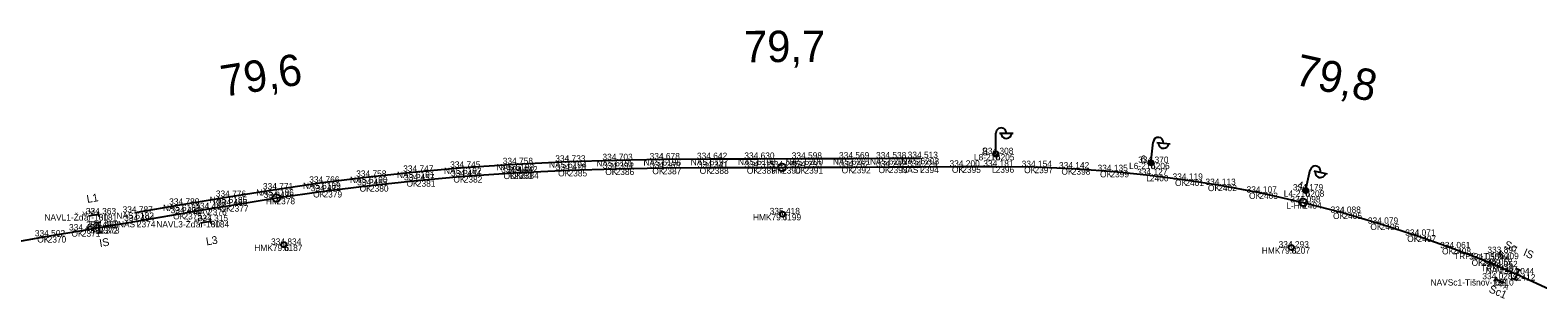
# Model space of a CAD drawing. Extents: x -621782 to -610392, y -1141853 to -1122321.
# Drawn here: x -614776.2 to -614487.1, y -1129952.4 to -1129901 of the extents above; entities that cross this region are included whole.
import ezdxf

# ---------------------------------------------------------------- set-up
doc = ezdxf.new("R2010")
doc.units = 0
for name, color, linetype in [('Vrstva 1', 7, 'Continuous'), ('Vrstva 14', 7, 'Continuous'), ('Vrstva 25', 7, 'Continuous'), ('Vrstva 3', 7, 'Continuous'), ('Vrstva 6', 7, 'Continuous'), ('Vrstva 60', 7, 'Continuous'), ('Vrstva 61', 7, 'Continuous'), ('Vrstva 62', 7, 'Continuous'), ('Vrstva 7', 7, 'Continuous')]:
    doc.layers.add(name, color=color, linetype=linetype)

msp = doc.modelspace()

# ---------------------------------------------------------------- linework, layer by layer
at = {"layer": 'Vrstva 1'}
msp.add_lwpolyline([(-614780.67, -1129941.78), (-614772.86, -1129940.43), (-614766.31, -1129939.31), (-614763.01, -1129938.75), (-614762.64, -1129938.69), (-614755.75, -1129937.51), (-614746.82, -1129936), (-614742.1, -1129935.2), (-614737.91, -1129934.51), (-614728.99, -1129933.09), (-614719.97, -1129931.79), (-614711.06, -1129930.68), (-614702.07, -1129929.73), (-614693.08, -1129928.94), (-614683.45, -1129928.28), (-614682.27, -1129928.21), (-614672.99, -1129927.77), (-614663.96, -1129927.5), (-614654.93, -1129927.35), (-614645.85, -1129927.29), (-614636.81, -1129927.26), (-614632.05, -1129927.24), (-614627.75, -1129927.22), (-614618.62, -1129927.18), (-614611.56, -1129927.14), (-614605.56, -1129927.12), (-614597.49, -1129927.09), (-614591.1, -1129927.08), (-614583.65, -1129927.15), (-614576.5, -1129927.44), (-614569.09, -1129927.95), (-614561.51, -1129928.71), (-614554.72, -1129929.6), (-614548.41, -1129930.59), (-614540.53, -1129932.07), (-614532.14, -1129933.94), (-614524.42, -1129935.93), (-614517.27, -1129938.02), (-614510.19, -1129940.31), (-614503.51, -1129942.7), (-614497.84, -1129944.89), (-614495.32, -1129945.92), (-614494.35, -1129946.33), (-614491.18, -1129947.69), (-614484.18, -1129950.86)], dxfattribs=at)
at = {"layer": 'Vrstva 14'}
msp.add_lwpolyline([(-614756.04, -1129935.88), (-614747.11, -1129934.37), (-614738.16, -1129932.87), (-614729.23, -1129931.45), (-614720.24, -1129930.16), (-614711.25, -1129929.03), (-614702.24, -1129928.07), (-614693.22, -1129927.29), (-614683.15, -1129926.61), (-614673.08, -1129926.12), (-614664.03, -1129925.84), (-614654.98, -1129925.69), (-614645.91, -1129925.63), (-614636.83, -1129925.59), (-614627.74, -1129925.56), (-614618.67, -1129925.52), (-614611.57, -1129925.49), (-614605.5, -1129925.45)], dxfattribs=at)
at = {"layer": 'Vrstva 25'}
for p, q in [((-614591.04, -1129924.19), (-614591.05, -1129920.69)), ((-614590.35, -1129920.69), (-614587.75, -1129920.68)), ((-614561.25, -1129925.88), (-614560.9, -1129922.39)), ((-614560.21, -1129922.46), (-614557.62, -1129922.72)), ((-614591.52, -1129924.84), (-614590.9, -1129924.21)), ((-614591.28, -1129925.13), (-614590.6, -1129924.45)), ((-614561.79, -1129926.47), (-614561.11, -1129925.91)), ((-614561.58, -1129926.78), (-614560.84, -1129926.18)), ((-614531.54, -1129931.16), (-614530.78, -1129927.74)), ((-614530.09, -1129927.89), (-614527.55, -1129928.46)), ((-614532.14, -1129931.69), (-614531.4, -1129931.21)), ((-614531.97, -1129932.02), (-614531.17, -1129931.51))]:
    msp.add_line(p, q, dxfattribs=at)
for centre in [(-614591.04, -1129924.69), (-614561.3, -1129926.37), (-614531.65, -1129931.65)]:
    msp.add_circle(centre, 0.5, dxfattribs=at)
for centre, start, end in [((-614590.05, -1129920.69), 0.0807, 180.0807), ((-614589.05, -1129920.7), 179.3782, 0.7833), ((-614559.91, -1129922.49), 354.2782, 174.2782), ((-614558.91, -1129922.6), 173.5756, 354.9808), ((-614529.8, -1129927.96), 347.4437, 167.4437), ((-614528.83, -1129928.19), 166.7411, 348.1463)]:
    msp.add_arc(centre, 1, start, end, dxfattribs=at)
at = {"layer": 'Vrstva 3'}
for p, q in [((-614763.67, -1129937.85), (-614762.68, -1129937.68)), ((-614763.17, -1129937.76), (-614762.84, -1129939.73)), ((-614763.33, -1129939.82), (-614762.34, -1129939.65)), ((-614490.79, -1129946.77), (-614491.57, -1129948.61)), ((-614491.24, -1129946.57), (-614490.33, -1129946.96)), ((-614492.03, -1129948.41), (-614491.11, -1129948.8))]:
    msp.add_line(p, q, dxfattribs=at)
at = {"layer": 'Vrstva 6'}
for p, q in [((-614765.03, -1129936.54), (-614763.08, -1129936.21)), ((-614763, -1129936.7), (-614763.16, -1129935.72)), ((-614743.57, -1129937.86), (-614741.62, -1129937.53)), ((-614741.53, -1129938.02), (-614741.7, -1129937.03)), ((-614494.55, -1129944.06), (-614494.17, -1129943.14)), ((-614495.13, -1129948.19), (-614495.52, -1129949.11)), ((-614493.51, -1129949.43), (-614495.33, -1129948.65))]:
    msp.add_line(p, q, dxfattribs=at)
at = {"layer": 'Vrstva 60'}
for p, q in [((-614683.15, -1129926.61), (-614683.15, -1129926.61)), ((-614673.08, -1129926.12), (-614673.08, -1129926.12)), ((-614664.03, -1129925.84), (-614664.03, -1129925.84)), ((-614654.98, -1129925.69), (-614654.98, -1129925.69)), ((-614645.91, -1129925.63), (-614645.91, -1129925.63)), ((-614636.83, -1129925.59), (-614636.83, -1129925.59)), ((-614627.74, -1129925.56), (-614627.74, -1129925.56)), ((-614618.67, -1129925.52), (-614618.67, -1129925.52)), ((-614611.57, -1129925.49), (-614611.57, -1129925.49)), ((-614605.5, -1129925.45), (-614605.5, -1129925.45)), ((-614591.04, -1129924.69), (-614591.04, -1129924.69)), ((-614561.3, -1129926.37), (-614561.3, -1129926.37)), ((-614711.25, -1129929.03), (-614711.25, -1129929.03)), ((-614702.24, -1129928.07), (-614702.24, -1129928.07)), ((-614693.22, -1129927.29), (-614693.22, -1129927.29)), ((-614693.08, -1129928.94), (-614693.08, -1129928.94)), ((-614683.45, -1129928.28), (-614683.45, -1129928.28)), ((-614682.27, -1129928.21), (-614682.27, -1129928.21)), ((-614672.99, -1129927.77), (-614672.99, -1129927.77)), ((-614663.96, -1129927.5), (-614663.96, -1129927.5)), ((-614654.93, -1129927.35), (-614654.93, -1129927.35)), ((-614645.85, -1129927.29), (-614645.85, -1129927.29)), ((-614636.81, -1129927.26), (-614636.81, -1129927.26)), ((-614632.05, -1129927.24), (-614632.05, -1129927.24)), ((-614627.75, -1129927.22), (-614627.75, -1129927.22)), ((-614618.62, -1129927.18), (-614618.62, -1129927.18)), ((-614611.56, -1129927.14), (-614611.56, -1129927.14)), ((-614605.56, -1129927.12), (-614605.56, -1129927.12)), ((-614597.49, -1129927.09), (-614597.49, -1129927.09)), ((-614591.1, -1129927.08), (-614591.1, -1129927.08)), ((-614583.65, -1129927.15), (-614583.65, -1129927.15)), ((-614576.5, -1129927.44), (-614576.5, -1129927.44)), ((-614569.09, -1129927.95), (-614569.09, -1129927.95)), ((-614561.51, -1129928.71), (-614561.51, -1129928.71)), ((-614554.72, -1129929.6), (-614554.72, -1129929.6)), ((-614729.23, -1129931.45), (-614729.23, -1129931.45)), ((-614720.24, -1129930.16), (-614720.24, -1129930.16)), ((-614719.97, -1129931.79), (-614719.97, -1129931.79)), ((-614711.06, -1129930.68), (-614711.06, -1129930.68)), ((-614702.07, -1129929.73), (-614702.07, -1129929.73)), ((-614548.41, -1129930.59), (-614548.41, -1129930.59)), ((-614540.53, -1129932.07), (-614540.53, -1129932.07)), ((-614531.65, -1129931.65), (-614531.65, -1129931.65)), ((-614747.11, -1129934.37), (-614747.11, -1129934.37)), ((-614742.1, -1129935.2), (-614742.1, -1129935.2)), ((-614738.16, -1129932.87), (-614738.16, -1129932.87)), ((-614737.91, -1129934.51), (-614737.91, -1129934.51)), ((-614728.99, -1129933.09), (-614728.99, -1129933.09)), ((-614532.14, -1129933.94), (-614532.14, -1129933.94)), ((-614763.08, -1129936.21), (-614763.08, -1129936.21)), ((-614756.04, -1129935.88), (-614756.04, -1129935.88)), ((-614755.75, -1129937.51), (-614755.75, -1129937.51)), ((-614746.82, -1129936), (-614746.82, -1129936)), ((-614741.62, -1129937.53), (-614741.62, -1129937.53)), ((-614631.96, -1129936.19), (-614631.96, -1129936.19)), ((-614524.42, -1129935.93), (-614524.42, -1129935.93)), ((-614517.27, -1129938.02), (-614517.27, -1129938.02)), ((-614772.86, -1129940.43), (-614772.86, -1129940.43)), ((-614766.31, -1129939.31), (-614766.31, -1129939.31)), ((-614763.01, -1129938.75), (-614763.01, -1129938.75)), ((-614762.64, -1129938.69), (-614762.64, -1129938.69)), ((-614510.19, -1129940.31), (-614510.19, -1129940.31)), ((-614727.57, -1129942.04), (-614727.57, -1129942.04)), ((-614534.39, -1129942.56), (-614534.39, -1129942.56)), ((-614503.51, -1129942.7), (-614503.51, -1129942.7)), ((-614494.36, -1129943.6), (-614494.36, -1129943.6)), ((-614497.84, -1129944.89), (-614497.84, -1129944.89)), ((-614495.32, -1129945.92), (-614495.32, -1129945.92)), ((-614494.35, -1129946.33), (-614494.35, -1129946.33)), ((-614495.33, -1129948.65), (-614495.33, -1129948.65)), ((-614491.18, -1129947.69), (-614491.18, -1129947.69))]:
    msp.add_line(p, q, dxfattribs=at)
at = {"layer": 'Vrstva 7'}
for p, q in [((-614632.01, -1129936.19), (-614631.91, -1129936.19)), ((-614727.61, -1129942.05), (-614727.52, -1129942.04)), ((-614534.44, -1129942.55), (-614534.34, -1129942.57))]:
    msp.add_line(p, q, dxfattribs=at)
for centre, radius in [((-614632.05, -1129927.24), 0.75), ((-614728.99, -1129933.09), 0.75), ((-614532.14, -1129933.94), 0.75), ((-614631.96, -1129936.19), 0.5), ((-614727.57, -1129942.04), 0.5), ((-614534.39, -1129942.56), 0.5)]:
    msp.add_circle(centre, radius, dxfattribs=at)

# ---------------------------------------------------------------- texts
at = {"layer": 'Vrstva 25'}
for s, rotation, p in [('8', 0.0807, (-614593.71, -1129924.95)), ('6', 354.2782, (-614563.4, -1129926.4)), ('4', 347.4437, (-614533.39, -1129931.29))]:
    msp.add_text(s, height=1.5, rotation=rotation, dxfattribs=at).set_placement(p)
at = {"layer": 'Vrstva 3'}
for rotation, p in [(9.6646, (-614762.81, -1129942.5)), (336.8123, (-614490.06, -1129944.08))]:
    msp.add_text('IS', height=1.5, rotation=rotation, dxfattribs=at).set_placement(p)
at = {"layer": 'Vrstva 6'}
for s, height, rotation, p in [('L1', 1.5, 9.7118, (-614765.24, -1129934.06)), ('  A A ', 1, 189.7118, (-614763.25, -1129935.22)), ('  A A ', 1, 189.6079, (-614741.78, -1129936.54)), ('L3', 1.5, 9.6079, (-614742.37, -1129942.18)), ('A A ', 1, 337.7412, (-614494.74, -1129944.53)), ('Sc', 1.5, 337.7412, (-614493.7, -1129942.58)), ('Sc1', 1.5, 336.8123, (-614496.65, -1129951.07)), ('  A A ', 1, 336.8123, (-614495.72, -1129949.57))]:
    msp.add_text(s, height=height, rotation=rotation, dxfattribs=at).set_placement(p)
at = {"layer": 'Vrstva 60'}
for s, p in [('6193', (-614683.15, -1129927.81)), ('6194', (-614673.08, -1129927.32)), ('6195', (-614664.03, -1129927.04)), ('6196', (-614654.98, -1129926.89)), ('6197', (-614645.91, -1129926.83)), ('6198', (-614636.83, -1129926.79)), ('6200', (-614627.74, -1129926.76)), ('6201', (-614618.67, -1129926.72)), ('6202', (-614611.57, -1129926.69)), ('6203', (-614605.5, -1129926.65)), ('6205', (-614591.04, -1129925.89)), ('6206', (-614561.3, -1129927.57)), ('6190', (-614711.25, -1129930.23)), ('6191', (-614702.24, -1129929.27)), ('6192', (-614693.22, -1129928.49)), ('2382', (-614693.08, -1129930.14)), ('2383', (-614683.45, -1129929.48)), ('2384', (-614682.27, -1129929.41)), ('2385', (-614672.99, -1129928.97)), ('2386', (-614663.96, -1129928.7)), ('2387', (-614654.93, -1129928.55)), ('2388', (-614645.85, -1129928.49)), ('2389', (-614636.81, -1129928.46)), ('2390', (-614632.05, -1129928.44)), ('2391', (-614627.75, -1129928.42)), ('2392', (-614618.62, -1129928.38)), ('2393', (-614611.56, -1129928.34)), ('2394', (-614605.56, -1129928.32)), ('2395', (-614597.49, -1129928.29)), ('2396', (-614591.1, -1129928.28)), ('2397', (-614583.65, -1129928.35)), ('2398', (-614576.5, -1129928.64)), ('2399', (-614569.09, -1129929.15)), ('2400', (-614561.51, -1129929.91)), ('2401', (-614554.72, -1129930.8)), ('6186', (-614729.23, -1129932.65)), ('6189', (-614720.24, -1129931.36)), ('2379', (-614719.97, -1129933)), ('2380', (-614711.06, -1129931.88)), ('2381', (-614702.07, -1129930.93)), ('2402', (-614548.41, -1129931.79)), ('2403', (-614540.53, -1129933.27)), ('6208', (-614531.65, -1129932.85)), ('6183', (-614747.11, -1129935.57)), ('2376', (-614742.1, -1129936.4)), ('6185', (-614738.16, -1129934.07)), ('2377', (-614737.91, -1129935.71)), ('2378', (-614728.99, -1129934.29)), ('2404', (-614532.14, -1129935.14)), ('6181', (-614763.08, -1129937.41)), ('6182', (-614756.04, -1129937.08)), ('2374', (-614755.75, -1129938.71)), ('2375', (-614746.82, -1129937.2)), ('6184', (-614741.62, -1129938.73)), ('6199', (-614631.96, -1129937.39)), ('2405', (-614524.42, -1129937.13)), ('2406', (-614517.27, -1129939.22)), ('2370', (-614772.86, -1129941.63)), ('2371', (-614766.31, -1129940.51)), ('2372', (-614763.01, -1129939.95)), ('2373', (-614762.64, -1129939.89)), ('2407', (-614510.19, -1129941.51)), ('6187', (-614727.57, -1129943.24)), ('6207', (-614534.39, -1129943.76)), ('2408', (-614503.51, -1129943.9)), ('6209', (-614494.36, -1129944.8)), ('2409', (-614497.84, -1129946.09)), ('2410', (-614495.32, -1129947.12)), ('2411', (-614494.35, -1129947.53)), ('6210', (-614495.33, -1129949.85)), ('2412', (-614491.18, -1129948.89))]:
    msp.add_text(s, height=1.2, dxfattribs=at).set_placement(p)
at = {"layer": 'Vrstva 61'}
for s, p in [('334.308', (-614593.49, -1129924.69)), ('334.745', (-614695.68, -1129927.29)), ('334.758', (-614685.6, -1129926.61)), ('334.733', (-614675.53, -1129926.12)), ('334.418', (-614675.45, -1129927.77)), ('334.703', (-614666.48, -1129925.84)), ('334.394', (-614666.41, -1129927.5)), ('334.678', (-614657.44, -1129925.69)), ('334.369', (-614657.38, -1129927.35)), ('334.642', (-614648.36, -1129925.63)), ('334.341', (-614648.21, -1129927.29)), ('334.630', (-614639.28, -1129925.59)), ('334.315', (-614639.26, -1129927.26)), ('334.285', (-614634.51, -1129927.24)), ('334.293', (-614630.21, -1129927.22)), ('334.598', (-614630.19, -1129925.56)), ('334.569', (-614621.12, -1129925.52)), ('334.262', (-614621.07, -1129927.18)), ('334.538', (-614614.02, -1129925.49)), ('334.242', (-614614.01, -1129927.14)), ('334.224', (-614608.01, -1129927.12)), ('334.513', (-614607.96, -1129925.45)), ('334.200', (-614599.94, -1129927.09)), ('334.181', (-614593.46, -1129927.08)), ('334.154', (-614586.1, -1129927.15)), ('334.142', (-614578.95, -1129927.44)), ('334.135', (-614571.55, -1129927.95)), ('334.370', (-614563.75, -1129926.37)), ('334.766', (-614722.7, -1129930.16)), ('334.758', (-614713.7, -1129929.03)), ('334.465', (-614713.52, -1129930.68)), ('334.747', (-614704.69, -1129928.07)), ('334.457', (-614704.52, -1129929.73)), ('334.454', (-614695.53, -1129928.94)), ('334.442', (-614685.9, -1129928.28)), ('334.442', (-614684.71, -1129928.21)), ('334.127', (-614563.96, -1129928.71)), ('334.119', (-614557.17, -1129929.6)), ('334.113', (-614550.86, -1129930.59)), ('334.776', (-614740.61, -1129932.87)), ('334.771', (-614731.58, -1129931.45)), ('334.478', (-614731.44, -1129933.09)), ('334.472', (-614722.42, -1129931.79)), ('334.107', (-614542.98, -1129932.07)), ('334.179', (-614534.1, -1129931.65)), ('334.363', (-614765.53, -1129936.21)), ('334.787', (-614758.49, -1129935.88)), ('334.780', (-614749.56, -1129934.37)), ('334.490', (-614749.27, -1129936)), ('334.487', (-614744.55, -1129935.2)), ('334.485', (-614740.37, -1129934.51)), ('335.418', (-614634.42, -1129936.19)), ('334.098', (-614534.59, -1129933.94)), ('334.088', (-614526.87, -1129935.93)), ('334.498', (-614768.76, -1129939.31)), ('334.493', (-614765.46, -1129938.75)), ('334.493', (-614765.09, -1129938.69)), ('334.494', (-614758.2, -1129937.51)), ('334.315', (-614744.07, -1129937.53)), ('334.079', (-614519.72, -1129938.02)), ('334.502', (-614775.31, -1129940.43)), ('334.834', (-614730.02, -1129942.04)), ('334.071', (-614512.55, -1129940.31)), ('334.293', (-614536.84, -1129942.56)), ('334.061', (-614505.87, -1129942.7)), ('334.055', (-614500.3, -1129944.89)), ('333.897', (-614496.81, -1129943.6)), ('334.052', (-614497.77, -1129945.92)), ('334.052', (-614496.8, -1129946.33)), ('334.044', (-614493.63, -1129947.69)), ('334.028', (-614497.78, -1129948.65))]:
    msp.add_text(s, height=1.2, dxfattribs=at).set_placement(p)
at = {"layer": 'Vrstva 62'}
for s, p in [('NAST', (-614686.79, -1129927.81)), ('NAST', (-614676.72, -1129927.32)), ('NAST', (-614667.67, -1129927.04)), ('NAST', (-614658.62, -1129926.89)), ('NAST', (-614649.55, -1129926.83)), ('NAST', (-614640.47, -1129926.79)), ('NAST', (-614631.38, -1129926.76)), ('NAST', (-614622.31, -1129926.72)), ('NAST', (-614615.21, -1129926.69)), ('NAST', (-614609.14, -1129926.65)), ('L8-210', (-614595.25, -1129925.89)), ('L6-210', (-614565.51, -1129927.57)), ('NAST', (-614714.89, -1129930.23)), ('NAST', (-614705.88, -1129929.27)), ('NAST', (-614696.86, -1129928.49)), ('OK', (-614695.06, -1129930.14)), ('OK', (-614685.44, -1129929.48)), ('OK', (-614684.25, -1129929.41)), ('OK', (-614674.98, -1129928.97)), ('OK', (-614665.94, -1129928.7)), ('OK', (-614656.92, -1129928.55)), ('OK', (-614647.84, -1129928.49)), ('OK', (-614638.79, -1129928.46)), ('HM', (-614634.08, -1129928.44)), ('OK', (-614629.74, -1129928.42)), ('OK', (-614620.61, -1129928.38)), ('OK', (-614613.55, -1129928.34)), ('NAST', (-614609.2, -1129928.32)), ('OK', (-614599.47, -1129928.29)), ('L', (-614591.81, -1129928.28)), ('OK', (-614585.63, -1129928.35)), ('OK', (-614578.48, -1129928.64)), ('OK', (-614571.08, -1129929.15)), ('L', (-614562.22, -1129929.91)), ('OK', (-614556.7, -1129930.8)), ('NAST', (-614732.87, -1129932.65)), ('NAST', (-614723.88, -1129931.36)), ('OK', (-614721.95, -1129933)), ('OK', (-614713.04, -1129931.88)), ('OK', (-614704.05, -1129930.93)), ('OK', (-614550.39, -1129931.79)), ('OK', (-614542.51, -1129933.27)), ('L4-210', (-614535.86, -1129932.85)), ('NAST', (-614750.75, -1129935.57)), ('NAV', (-614744.91, -1129936.4)), ('NAST', (-614741.79, -1129934.07)), ('OK', (-614739.9, -1129935.71)), ('HM', (-614731.02, -1129934.29)), ('L-HM', (-614535.39, -1129935.14)), ('NAVL1-Žďár-130', (-614773.48, -1129937.41)), ('NAST', (-614759.68, -1129937.08)), ('NAST', (-614759.39, -1129938.71)), ('NAVL3-Žďár-130', (-614752.02, -1129938.73)), ('OK', (-614748.8, -1129937.2)), ('HMK79.7', (-614637.63, -1129937.39)), ('OK', (-614526.4, -1129937.13)), ('OK', (-614519.25, -1129939.22)), ('OK', (-614774.85, -1129941.63)), ('OK', (-614768.3, -1129940.51)), ('NAV', (-614765.46, -1129939.89)), ('IS', (-614764.23, -1129939.95)), ('OK', (-614512.18, -1129941.51)), ('HMK79.6', (-614733.23, -1129943.24)), ('HMK79.8', (-614540.06, -1129943.76)), ('OK', (-614505.5, -1129943.9)), ('TRPSc-Tišnov', (-614503.2, -1129944.8)), ('OK', (-614499.83, -1129946.09)), ('TRP', (-614498.01, -1129947.12)), ('NAV', (-614497.16, -1129947.53)), ('NAVSc1-Tišnov-130', (-614507.71, -1129949.85)), ('IS', (-614492.41, -1129948.89))]:
    msp.add_text(s, height=1.2, dxfattribs=at).set_placement(p)
at = {"layer": 'Vrstva 7'}
for s, rotation, p in [('79,7', 0.2667, (-614639.35, -1129907.12)), ('79,6', 9.0036, (-614739.18, -1129913.77)), ('79,8', 347.4437, (-614534.02, -1129911.34))]:
    msp.add_text(s, height=6, rotation=rotation, dxfattribs=at).set_placement(p)

doc.saveas('drawing.dxf')
